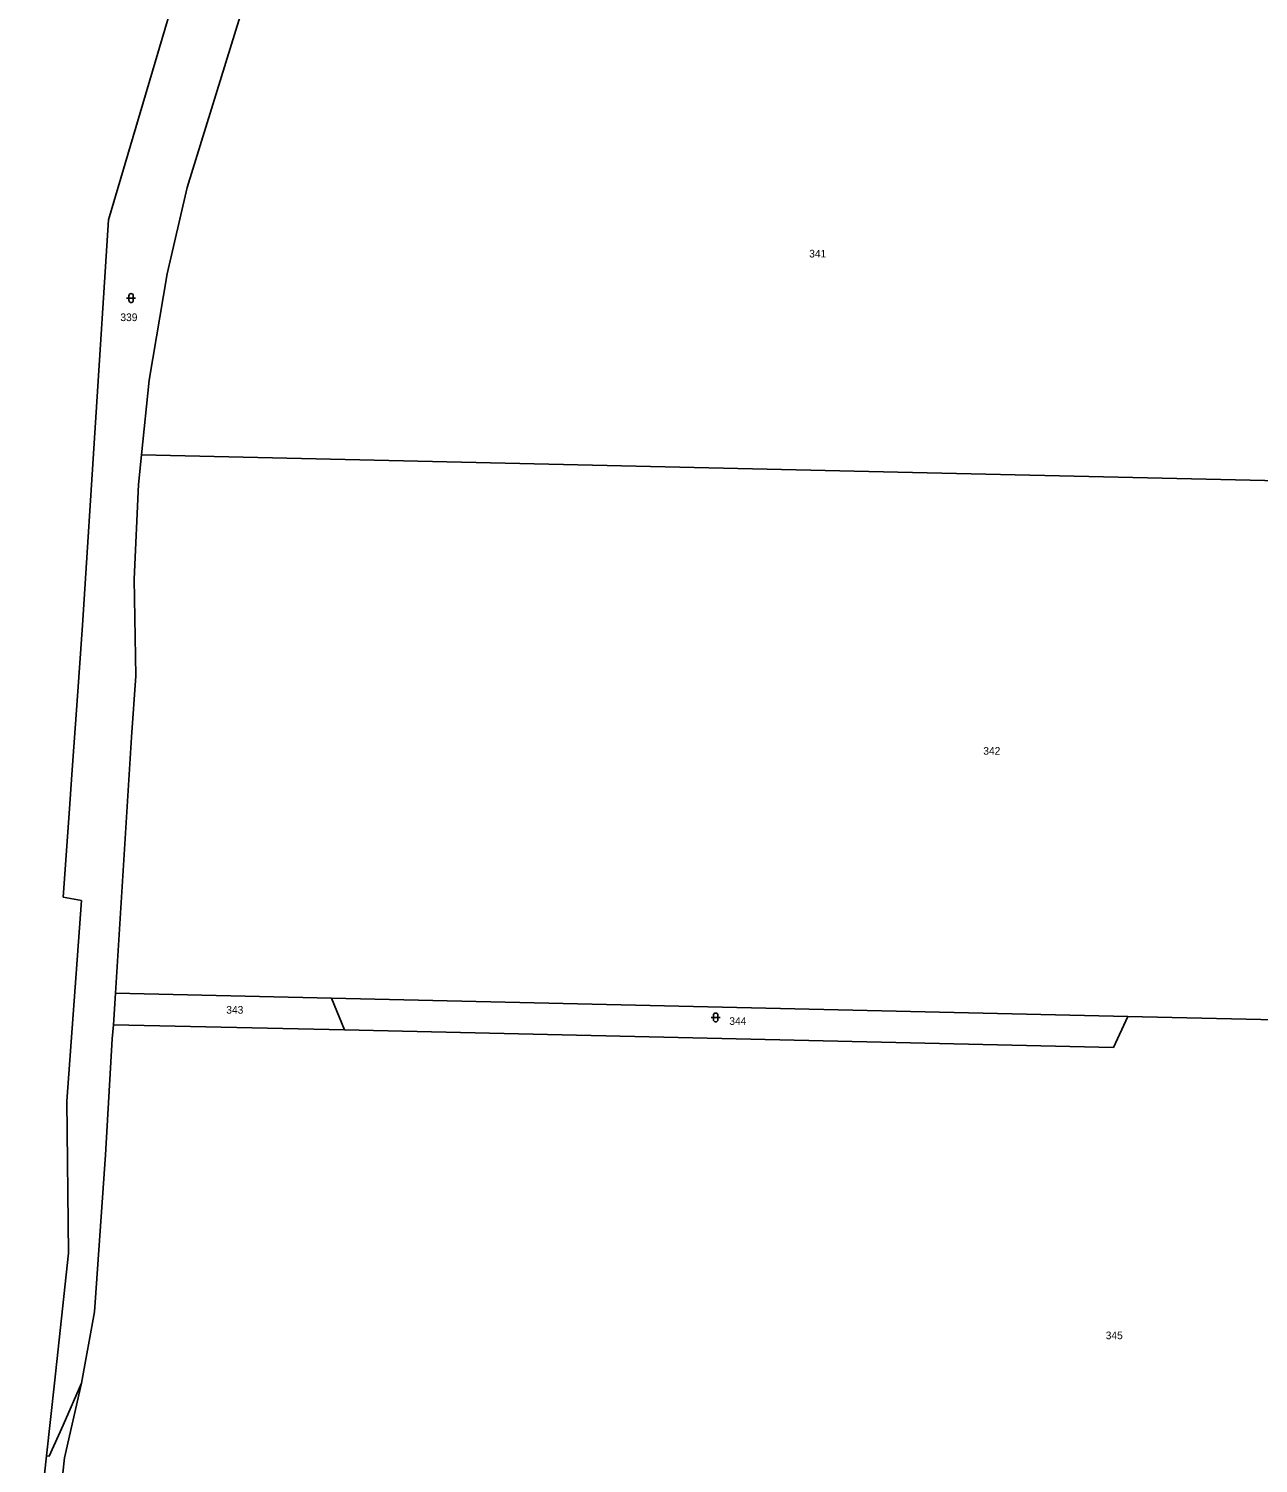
# Model space of a CAD drawing. Extents: x -769392 to -767038, y -1018329 to -1015269.
# Drawn here: x -769084.1 to -768810.3, y -1016085.5 to -1015766.2 of the extents above; entities that cross this region are included whole.
import ezdxf

# ---------------------------------------------------------------- set-up
doc = ezdxf.new("R2010")
doc.units = 0
doc.header["$LTSCALE"] = 0.68
doc.layers.add('1', color=7, linetype='Continuous', lineweight=25)
doc.layers.add('3', color=7, linetype='Continuous', lineweight=25)
doc.layers.add('2', color=7, linetype='Continuous')

msp = doc.modelspace()

# ---------------------------------------------------------------- linework, layer by layer
at = {"layer": '1'}
for p, q in [((-769066.34, -1015808.74), (-769047.08, -1015743.67)), ((-769072.12, -1015898.98), (-769066.34, -1015808.74)), ((-769073.34, -1015915.82), (-769072.12, -1015898.98)), ((-769074.45, -1015931.18), (-769073.34, -1015915.82)), ((-769075.07, -1015940.9), (-769074.45, -1015931.18)), ((-769076.45, -1015959.49), (-769075.07, -1015940.9)), ((-769076.45, -1015959.49), (-769072.34, -1015960.27)), ((-769065.22, -1015987.9), (-769064.78, -1015980.91)), ((-769016.65, -1015982.01), (-769064.78, -1015980.91)), ((-769013.82, -1015989.07), (-769016.65, -1015982.01)), ((-768839.41, -1015986.06), (-769016.65, -1015982.01)), ((-769013.82, -1015989.07), (-769065.22, -1015987.9)), ((-768647.11, -1015990.45), (-768839.41, -1015986.06)), ((-769078.38, -1016067.71), (-769080.14, -1016083.85)), ((-769080.14, -1016083.85), (-769084.11, -1016120.36))]:
    msp.add_line(p, q, dxfattribs=at)
for points in [[(-769059, -1015861.06), (-769057.3, -1015844.46), (-769053.28, -1015820.77), (-769048.84, -1015801.56), (-769037, -1015763.4), (-769030.08, -1015745.22), (-769027.63, -1015735.68)], [(-769064.78, -1015980.91), (-769061.19, -1015923.91), (-769060.24, -1015910.23), (-769060.63, -1015888.77), (-769059.68, -1015867.68), (-769059, -1015861.06)], [(-769059, -1015861.06), (-768887.32, -1015864.98), (-768723.8, -1015868.72)], [(-769072.34, -1015960.27), (-769075.65, -1016004.94), (-769075.22, -1016038.74), (-769078.38, -1016067.71)], [(-769072.33, -1016067.68), (-769069.46, -1016051.83), (-769067.04, -1016016.89), (-769065.51, -1015991.03), (-769065.22, -1015987.9)], [(-768839.41, -1015986.06), (-768842.57, -1015992.98), (-769013.82, -1015989.07)], [(-769080.14, -1016083.85), (-769079.52, -1016083.92), (-769076.44, -1016076.99), (-769072.33, -1016067.68)], [(-769072.33, -1016067.68), (-769076.16, -1016084.29), (-769079.86, -1016118.25), (-769077.57, -1016120.97)]]:
    msp.add_lwpolyline(points, dxfattribs=at)
at = {"layer": '3'}
for p, q in [((-769062.311, -1015826.181), (-769060.309, -1015826.181)), ((-769061.811, -1015825.681), (-769061.811, -1015826.682)), ((-769060.809, -1015826.682), (-769060.809, -1015825.681)), ((-768932.151, -1015986.291), (-768930.149, -1015986.291)), ((-768931.651, -1015985.791), (-768931.651, -1015986.792)), ((-768930.649, -1015986.792), (-768930.649, -1015985.791))]:
    msp.add_line(p, q, dxfattribs=at)
for centre, start, end in [((-769061.31, -1015825.6809), 0, 180), ((-769061.31, -1015826.6809), 180, 359.98789), ((-768931.15, -1015985.7909), 0, 180), ((-768931.15, -1015986.7909), 180, 359.98789)]:
    msp.add_arc(centre, 0.5, start, end, dxfattribs=at)

# ---------------------------------------------------------------- texts
at = {"layer": '2'}
for s, p in [('341', (-768910.32, -1015817.135)), ('339', (-769063.69, -1015831.295)), ('342', (-768871.56, -1015927.805)), ('343', (-769040.11, -1015985.435)), ('344', (-768928.11, -1015987.935)), ('345', (-768844.3, -1016057.895))]:
    msp.add_text(s, height=1.7, dxfattribs=at).set_placement(p)

doc.saveas('drawing.dxf')
